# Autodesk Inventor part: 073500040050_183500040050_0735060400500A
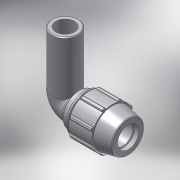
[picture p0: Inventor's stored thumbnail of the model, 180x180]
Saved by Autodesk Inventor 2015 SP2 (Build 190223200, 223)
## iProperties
Created: 2017-02
Part Number: 073500040050_183500040050_0735060400500A
Material: PVC-Piping
Description: PLASSON 90° ELBOW ADAPTOR 40-50
Document SubType Name: Modeling
Designer: KIM
Mass: 92.6774 g
Surface Area: 199.44 cm^2
Volume: 66.1981 cm^3
Density: 1.4 g/cm^3
Appearance: Smooth - White
Author: KIM
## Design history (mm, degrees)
derived "07350.ipt"
feature "Solid1::07350.ipt"
tag "TaggingFeature1"
body "Solid1"
other parameters: "d4" = 9.83333, "d5" = 29.5, "d7" = 82, "d11" = 3.93333, "d13" = 120 deg, "d15" = 12 deg, "d16" = 71.34, "d18" = 2, "d19" = 35 deg, "d20" = 17.5 deg, "d21" = 76.26, "d23" = 0, "d25" = 360 deg, "d27" = 1.64, "d33" = 0.8, "d42" = 43.66, "d43" = 2.46, "d46" = 1.2, "d51" = 118, "d68" = 3.93333, "d76" = 35, "d80" = 1.5, "d91" = 61.5, "d93" = 84, "d95" = 35, "d96" = 9.83333, "d97" = 50 deg, "d98" = 72, "d99" = 0, "d100" = 0, "E_" = 82, "A_" = 118, "l_" = 84
